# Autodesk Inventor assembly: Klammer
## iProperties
Shininess: 64.0
Length Units: 11269
Angle Units: 11279
Time Units: 11290
Mass Units: 11283
Length Display Precision: 3
Angle Display Precision: 2
Compacted: True
Created: 2004-08
Part Number: Klammer
Document SubType Name: Assembly
Designer: mp
Manufacturer: Standard
Standards Organization: Custom
Project: Original model by Michael Puschner
Density: 0.0
Volumn: 0.0
Area: 0.0
PropertySet Name: Model Information
Control State: 0
Master: False
Checked Out: False
Author: mp
Title: Inventor NG World Cup
Subject: Clothespin
